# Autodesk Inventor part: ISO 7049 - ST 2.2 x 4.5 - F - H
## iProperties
Author: Philippe
Created: 2002-01
Part Number: ISO 7049 - ST 2.2 x 4.5 - F - H
Material: Par défaut
Catalog Web Link: file:///C:/Program Files/Autodesk/Inventor 5/Content/Iso/index.htm?doNavigateId=B644153E-6486-4C49-BA92-F814F384E778|E6B68DE9D40241F9B23975AE3FB91F3E|true
Description: Vis à métaux
Document SubType Name: Standard Catalog Part
Standard: ISO 7049 - ST 2.2 x 4.5 - F - H
Designer: Philippe
CLASSIFICATION: 31161506 un/spsc
MANUFACTURER: ISO Système de normes
Control State: 0
Master: False
Checked Out: False
PropertySet Name: Design Tracking Control
Shininess: 20.0
Angle Display Precision: 2
Document Length Units: 11269
Document Angle Units: 11283
Document Time Units: 11279
Document Mass Units: 11290
Document Length Units Precision: 3
Document Angle Units Precision: 2
Compacted: False
PropertySet Name: _Private Model Information
Density: 0.0
Volumn: 0.0
Area: 0.0
PropertySet Name: Model Information
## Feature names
1. Base1
